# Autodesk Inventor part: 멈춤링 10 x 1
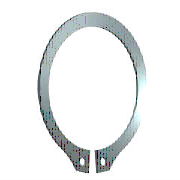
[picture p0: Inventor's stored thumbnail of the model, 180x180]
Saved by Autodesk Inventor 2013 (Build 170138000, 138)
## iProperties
IsCustomPart: 0
Company: 한국ATC센터
Created: 2014-07
Part Number: 멈춤링 10 x 1
Material: Steel, Mild
Description: 리테이닝 링(C형)
Document SubType Name: Modeling
Standard: KS B 1336
Designer: KYOUNG IL JANG
Standards Organization: KS
Language: ko-KR
Size Designation: 10 x 1
Categories: <MemberInstance><Categories><Category DisplayName="샤프트 부품" InternalName="7f7aeb1f-a693-4053-b835-cee3144e0d98" Mnemonic="SHFT"><Category DisplayName="써클립" Inter
Density: 7.86 g/cm^3
Mass: 0.423089 g
Surface Area: 1.9243 cm^2
Volume: 0.0538281 cm^3
Author: KYOUNG IL JANG
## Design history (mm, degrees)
sketch "스케치1"
  geometry: L1 (-6, 0)-(6, 0) reference; L2 (0, 20.189)-(0, -80.536) reference; L3 (-48.09, 0)-(48.09, 0) reference; L4 (-0.3, -9.791)-(-0.3, -12.791); L5 (-0.3, -6.54)-(-0.3, -13.29); L6 (-2.795, 1.6)-(3.672, 1.6); L7 (0.3, -6.54)-(0.3, -13.29); L8 (0.3, -9.791)-(0.3, -12.791); C1 r 0.6 at (-1.2, -11.486); C2 r 0.6 at (1.2, -11.486); A1 r 4.8 centre (0, -5) between (0.3, -9.791) and (-0.3, -9.791); A2 r 6.2 centre (0, -4.6) between (2.988, -10.033) and (-2.988, -10.033); A3 r 7.796 centre (0, -5) between (-1.418, -12.666) and (-0.3, -12.791); A4 r 1.2 centre (-1.2, -11.486) between (-2.383, -11.285) and (-1.418, -12.666); A5 r 1.2 centre (-3.566, -11.084) between (-2.383, -11.285) and (-2.988, -10.033); A6 r 1.2 centre (3.566, -11.084) between (2.988, -10.033) and (2.383, -11.285); A7 r 1.2 centre (1.2, -11.486) between (1.418, -12.666) and (2.383, -11.285); A8 r 7.796 centre (0, -5) between (0.3, -12.791) and (1.418, -12.666)
  constraints: 16 point on circle, 12 end point, 10 centre point, 9 symmetric about line, 5 point on line, 4 tangent, 3 coincident, 2 horizontal, 1 perpendicular, 1 vertical, 5 other
  dimensions: "d0" = 9.6 diameter of A1 (= ND); "d1" = 3 distance of L4.end L4.start (= SRB2); "d6" = 0.3 distance between parallel lines of L2 L5 (= 0.25 x SD5); "d7" = 1.6 distance between parallel lines of L6 L3 (= SRB1); "d8" = 0.4 distance of A1.centre A2.centre (= 0.25 x SRB1); "d9" = 1.2 radius of A4 (= SD5); "d10" = 1.2 radius of A5 (= SD5); "d11" = 0.9 distance from line of L4 A4.centre (= 0.75 x SD5); "d12" = 1.2 diameter of C1 (= SD5); "d13" = 1.2 diameter of C2 (= SD5); "d14" = 5 distance from line of A1.centre L1 (= 0.5 x WD)
extrude "본체" new body sketch "스케치1" distance "d2" = 1 (= SD); taper "d3" = 0 deg
workaxis "Work Axis1"
workplane "Work Plane1"
body "Solid1"
other parameters: "SD" = 1 [user parameter; used in 1 equation term], "SRB1" = 1.6 [user parameter; used in 2 equation terms], "ND" = 9.6 [user parameter; used in 1 equation term], "SRB2" = 3 [user parameter; used in 1 equation term], "SD5" = 1.2 [user parameter; used in 6 equation terms], "d15" = 0, "d16" = 0, "d17" = 0, "d41" = 0, "d42" = 0, "SD3" = 9.3 [user parameter], "WDMAX" = 11 [user parameter]
